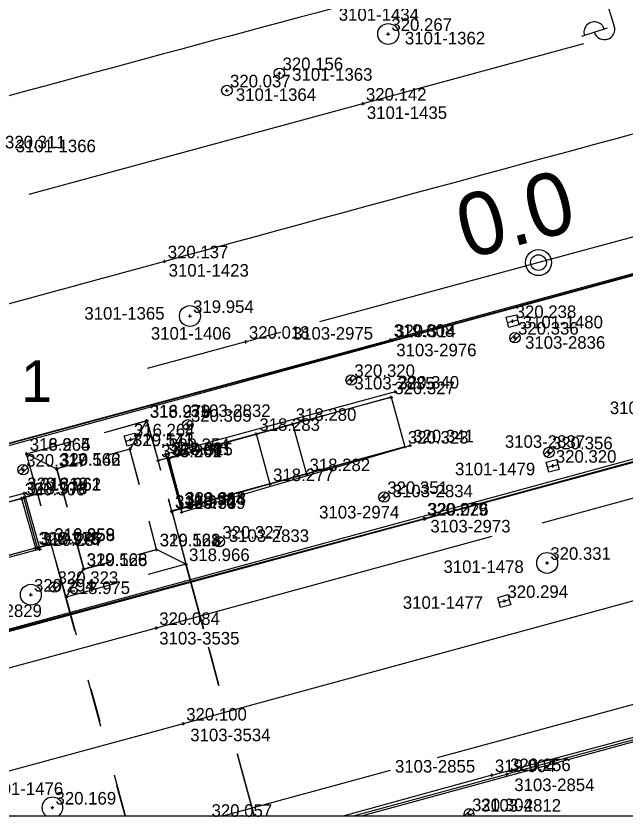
# Model space of a CAD drawing. Extents: x -821875 to -821475, y -1070280 to -1069975.
# Drawn here: x -821747.03 to -821717.84, y -1070250.06 to -1070211.76 of the extents above; entities that cross this region are included whole.
import ezdxf

# ---------------------------------------------------------------- set-up
doc = ezdxf.new("R2010")
doc.units = 0
for name, color, linetype in [('Vrstva 1', 7, 'Continuous'), ('Vrstva 14', 7, 'Continuous'), ('Vrstva 17', 7, 'Continuous'), ('Vrstva 18', 7, 'Continuous'), ('Vrstva 25', 7, 'Continuous'), ('Vrstva 3', 7, 'Continuous'), ('Vrstva 36', 7, 'Continuous'), ('Vrstva 43', 7, 'Continuous'), ('Vrstva 51', 7, 'Continuous'), ('Vrstva 60', 7, 'Continuous'), ('Vrstva 61', 7, 'Continuous'), ('Vrstva 7', 7, 'Continuous')]:
    doc.layers.add(name, color=color, linetype=linetype)

# ---------------------------------------------------------------- blocks, each defined once
blk = doc.blocks.new('BOD')
at = {"layer": 'Vrstva 3'}
for p, q in [((-0.15, 0), (0.15, 0)), ((0, -0.15), (0, 0.15))]:
    blk.add_line(p, q, dxfattribs=at)

msp = doc.modelspace()

# ---------------------------------------------------------------- linework, layer by layer
at = {"layer": 'Vrstva 1'}
msp.add_line((-821704.713, -1070218.861), (-821732.499, -1070226.383), dxfattribs=at)
msp.add_lwpolyline([(-821500, -1070000), (-821850, -1070000), (-821850, -1070250), (-821500, -1070250)], close=True, dxfattribs=at)
msp.add_lwpolyline([(-821500, -1070000), (-821850, -1070000), (-821850, -1070250), (-821500, -1070250)], close=True, dxfattribs=at)
for points in [[(-821719.872, -1070213.081), (-821746.41, -1070220.298)], [(-821682.027, -1070225.161), (-821721.87, -1070236.004)], [(-821667.464, -1070226.079), (-821669.621, -1070226.661), (-821739.032, -1070245.599)], [(-821724.264, -1070236.655), (-821740.322, -1070241.025)], [(-821688.161, -1070236.716), (-821726.868, -1070247.228)], [(-821740.322, -1070241.025), (-821750.102, -1070243.674)], [(-821739.032, -1070245.599), (-821755.257, -1070250)], [(-821729.131, -1070247.842), (-821737.076, -1070250)]]:
    msp.add_lwpolyline(points, dxfattribs=at)
for points in [[(-821710.276, -1070200.761), (-821741.264, -1070209.238), (-821760.235, -1070214.402), (-821776.338, -1070219.041), (-821794.464, -1070225.772), (-821811.866, -1070233.595), (-821823.5, -1070239.204)], [(-821742.542, -1070204.561), (-821755.391, -1070207.946), (-821768.915, -1070211.875), (-821773.964, -1070213.578)], [(-821709.336, -1070205.287), (-821731.872, -1070211.395), (-821757.763, -1070218.461), (-821767.367, -1070221.229)], [(-821705.268, -1070214.096), (-821739.917, -1070223.49), (-821760.504, -1070229.155), (-821769.875, -1070231.779)], [(-821734.361, -1070226.887), (-821736.033, -1070227.34), (-821740.744, -1070228.619)]]:
    msp.add_spline(points, degree=3, dxfattribs=at)
at = {"layer": 'Vrstva 14'}
for p, q in [((-821664.962, -1070209.896), (-821757.694, -1070235.105)), ((-821687.531, -1070215.9), (-821729.11, -1070227.249)), ((-821729.033, -1070227.268), (-821687.611, -1070215.993)), ((-821768.204, -1070246.736), (-821665.012, -1070218.658)), ((-821684.759, -1070224.159), (-821727.507, -1070235.797)), ((-821727.465, -1070235.8), (-821684.647, -1070224.184)), ((-821729.033, -1070227.268), (-821757.732, -1070234.994)), ((-821757.728, -1070234.967), (-821729.11, -1070227.249)), ((-821727.507, -1070235.797), (-821755.35, -1070243.283)), ((-821755.252, -1070243.318), (-821727.465, -1070235.8)), ((-821680.981, -1070236.519), (-821730.446, -1070250)), ((-821724.263, -1070248.063), (-821681.061, -1070236.453)), ((-821681.085, -1070236.494), (-821723.536, -1070248.016)), ((-821724.263, -1070248.063), (-821731.32, -1070250)), ((-821730.876, -1070250), (-821723.536, -1070248.016))]:
    msp.add_line(p, q, dxfattribs=at)
at = {"layer": 'Vrstva 17'}
for points in [[(-821728.878, -1070229.723), (-821739.859, -1070232.709), (-821739.095, -1070235.477), (-821728.172, -1070232.291)], [(-821757.433, -1070237.436), (-821746.637, -1070234.581), (-821745.884, -1070237.251), (-821756.709, -1070240.158)]]:
    msp.add_lwpolyline(points, dxfattribs=at)
at = {"layer": 'Vrstva 18'}
for points in [[(-821729.076, -1070229.992), (-821739.7, -1070232.918), (-821739.759, -1070232.897), (-821740.224, -1070233.006), (-821740.229, -1070233.009)], [(-821742.799, -1070231.675), (-821740.776, -1070231.121), (-821740.224, -1070233.006)], [(-821742.797, -1070231.666), (-821740.766, -1070231.104), (-821740.229, -1070233.009)], [(-821740.776, -1070231.121), (-821741.577, -1070232.469), (-821741.58, -1070232.475)], [(-821740.766, -1070231.104), (-821740.776, -1070231.121)], [(-821746.001, -1070234.589), (-821746.519, -1070232.695), (-821744.38, -1070232.109)], [(-821746.005, -1070234.604), (-821746.517, -1070232.694), (-821744.186, -1070232.05)], [(-821728.425, -1070232.355), (-821739.071, -1070235.273), (-821739.123, -1070235.308), (-821739.564, -1070235.427), (-821739.57, -1070235.452)], [(-821746.517, -1070232.694), (-821746.519, -1070232.695)], [(-821746.519, -1070232.695), (-821745.084, -1070233.412), (-821745.066, -1070233.409)], [(-821741.58, -1070232.475), (-821742.698, -1070232.775)], [(-821741.122, -1070234.175), (-821741.577, -1070232.469), (-821742.563, -1070232.734)], [(-821741.136, -1070234.137), (-821741.58, -1070232.475)], [(-821743.911, -1070233.097), (-821745.084, -1070233.412)], [(-821743.828, -1070233.077), (-821745.066, -1070233.409), (-821744.578, -1070235.24)], [(-821740.092, -1070233.492), (-821740.224, -1070233.006)], [(-821739.759, -1070232.897), (-821739.123, -1070235.308)], [(-821739.071, -1070235.273), (-821739.7, -1070232.918)], [(-821745.084, -1070233.412), (-821744.6, -1070235.212)], [(-821757.178, -1070237.66), (-821746.762, -1070234.831), (-821746.658, -1070234.777), (-821746.001, -1070234.589)], [(-821746.005, -1070234.604), (-821746.001, -1070234.589)], [(-821746.001, -1070234.589), (-821745.84, -1070235.176)], [(-821746.762, -1070234.831), (-821746.098, -1070237.192)], [(-821746, -1070237.183), (-821746.658, -1070234.777)], [(-821739.564, -1070235.427), (-821739.72, -1070234.854)], [(-821739.564, -1070235.427), (-821738.898, -1070237.973), (-821740.697, -1070238.468)], [(-821739.57, -1070235.452), (-821738.051, -1070241.063)], [(-821741.196, -1070237.502), (-821740.298, -1070237.262), (-821740.63, -1070236.018)], [(-821741.104, -1070237.487), (-821740.299, -1070237.27), (-821740.66, -1070235.918)], [(-821745.43, -1070236.675), (-821745.337, -1070237.015)], [(-821744.21, -1070236.623), (-821743.787, -1070238.211), (-821742.528, -1070237.871)], [(-821744.207, -1070236.678), (-821743.798, -1070238.198), (-821742.451, -1070237.838)], [(-821756.527, -1070240.021), (-821746.098, -1070237.192), (-821746, -1070237.183), (-821745.337, -1070237.015)], [(-821745.346, -1070237.001), (-821745.337, -1070237.015)], [(-821744.213, -1070241.16), (-821745.346, -1070237.001)], [(-821742.207, -1070238.884), (-821744.62, -1070239.549), (-821745.337, -1070237.015)], [(-821738.898, -1070237.973), (-821740.298, -1070237.262), (-821740.299, -1070237.27)], [(-821738.057, -1070241.071), (-821738.898, -1070237.973)], [(-821744.62, -1070239.549), (-821743.798, -1070238.198), (-821743.787, -1070238.211)], [(-821744.128, -1070241.361), (-821744.62, -1070239.549)], [(-821737.317, -1070243.793), (-821737.82, -1070241.943)], [(-821737.786, -1070242.043), (-821737.318, -1070243.77)], [(-821742.969, -1070245.726), (-821743.569, -1070243.523)], [(-821743.006, -1070245.496), (-821743.427, -1070243.943)], [(-821736.437, -1070247.026), (-821735.632, -1070250)], [(-821735.632, -1070250), (-821736.428, -1070247.07)], [(-821741.783, -1070250), (-821742.309, -1070248.061)], [(-821741.805, -1070250), (-821742.2, -1070248.548)]]:
    msp.add_lwpolyline(points, dxfattribs=at)
at = {"layer": 'Vrstva 25'}
for p, q in [((-821718.935, -1070210.57), (-821718.402, -1070212.237)), ((-821718.735, -1070212.343), (-821719.971, -1070212.74)), ((-821734.449, -1070214.495), (-821734.399, -1070214.495)), ((-821736.961, -1070215.319), (-821736.911, -1070215.319))]:
    msp.add_line(p, q, dxfattribs=at)
for centre in [(-821734.424, -1070214.495), (-821736.936, -1070215.319)]:
    msp.add_circle(centre, 0.25, dxfattribs=at)
for centre, start, end in [((-821719.354, -1070212.536), 17.1031, 198.5083), ((-821718.876, -1070212.389), 197.8057, 17.8057)]:
    msp.add_arc(centre, 0.5, start, end, dxfattribs=at)
at = {"layer": 'Vrstva 36'}
for p, q in [((-821723.386, -1070227.233), (-821723.064, -1070226.91)), ((-821723.256, -1070227.368), (-821722.929, -1070227.04)), ((-821731.218, -1070229.258), (-821730.896, -1070228.935)), ((-821731.088, -1070229.393), (-821730.761, -1070229.066)), ((-821739.036, -1070231.401), (-821738.714, -1070231.078)), ((-821738.906, -1070231.536), (-821738.579, -1070231.208)), ((-821721.76, -1070232.722), (-821721.438, -1070232.399)), ((-821721.63, -1070232.857), (-821721.303, -1070232.53)), ((-821746.92, -1070233.547), (-821746.596, -1070233.224)), ((-821746.79, -1070233.682), (-821746.462, -1070233.354)), ((-821729.642, -1070234.854), (-821729.32, -1070234.531)), ((-821729.512, -1070234.989), (-821729.185, -1070234.662)), ((-821737.534, -1070236.991), (-821737.21, -1070236.668)), ((-821737.404, -1070237.126), (-821737.076, -1070236.798)), ((-821745.416, -1070239.156), (-821745.092, -1070238.833)), ((-821745.286, -1070239.291), (-821744.958, -1070238.964)), ((-821725.561, -1070250), (-821725.26, -1070249.7)), ((-821725.296, -1070250), (-821725.126, -1070249.83))]:
    msp.add_line(p, q, dxfattribs=at)
for centre in [(-821723.156, -1070227.141), (-821730.988, -1070229.166), (-821738.806, -1070231.309), (-821721.53, -1070232.63), (-821746.689, -1070233.455), (-821729.412, -1070234.762), (-821737.303, -1070236.899), (-821745.185, -1070239.064)]:
    msp.add_circle(centre, 0.25, dxfattribs=at)
msp.add_arc((-821725.353, -1070249.931), 0.25, 343.9784, 196.0216, dxfattribs=at)
at = {"layer": 'Vrstva 43'}
for points in [[(-821723.513, -1070226.408), (-821723.573, -1070226.165), (-821723.087, -1070226.045), (-821722.967, -1070226.531), (-821723.453, -1070226.651), (-821723.513, -1070226.408), (-821723.027, -1070226.288)], [(-821741.773, -1070232.081), (-821741.844, -1070231.841), (-821741.364, -1070231.699), (-821741.222, -1070232.179), (-821741.702, -1070232.321), (-821741.773, -1070232.081), (-821741.293, -1070231.939)], [(-821721.591, -1070233.332), (-821721.655, -1070233.09), (-821721.171, -1070232.962), (-821721.043, -1070233.446), (-821721.527, -1070233.574), (-821721.591, -1070233.332), (-821721.107, -1070233.204)], [(-821723.423, -1070239.669), (-821723.357, -1070239.909), (-821723.839, -1070240.041), (-821723.971, -1070239.559), (-821723.489, -1070239.427), (-821723.423, -1070239.669), (-821723.905, -1070239.799)]]:
    msp.add_lwpolyline(points, dxfattribs=at)
for centre in [(-821729.217, -1070212.617), (-821738.704, -1070226.104), (-821721.614, -1070237.912), (-821746.314, -1070239.43)]:
    msp.add_circle(centre, 0.5, dxfattribs=at)
msp.add_arc((-821745.284, -1070249.615), 0.5, 309.6461, 230.3539, dxfattribs=at)
at = {"layer": 'Vrstva 51'}
for points in [[(-821733.791, -1070231.265), (-821729.076, -1070229.992), (-821728.425, -1070232.355), (-821733.132, -1070233.672)], [(-821735.532, -1070231.745), (-821733.791, -1070231.265), (-821733.132, -1070233.672), (-821734.876, -1070234.15)], [(-821740.229, -1070233.009), (-821735.532, -1070231.745), (-821734.876, -1070234.15), (-821739.57, -1070235.452), (-821739.729, -1070234.863)], [(-821740.118, -1070233.421), (-821740.229, -1070233.009)], [(-821750.714, -1070235.894), (-821746.005, -1070234.604), (-821745.854, -1070235.153)], [(-821745.448, -1070236.63), (-821745.346, -1070237.001), (-821750.05, -1070238.283)]]:
    msp.add_lwpolyline(points, dxfattribs=at)
at = {"layer": 'Vrstva 60'}
for p, q in [((-821725.428, -1070249.931), (-821725.278, -1070249.931)), ((-821725.353, -1070250), (-821725.353, -1070249.856))]:
    msp.add_line(p, q, dxfattribs=at)
at = {"layer": 'Vrstva 7'}
for radius in [0.623, 0.376]:
    msp.add_circle((-821722.028, -1070223.548), radius, dxfattribs=at)

# ---------------------------------------------------------------- block references
at = {"layer": 'Vrstva 60', "xscale": 0.5, "yscale": 0.5}
for p in [(-821729.217, -1070212.617), (-821734.424, -1070214.495), (-821736.936, -1070215.319), (-821730.434, -1070215.953), (-821739.917, -1070223.49), (-821738.704, -1070226.104), (-821723.27, -1070226.348), (-821736.033, -1070227.34), (-821729.11, -1070227.249), (-821729.033, -1070227.268), (-821723.156, -1070227.141), (-821730.988, -1070229.166), (-821728.878, -1070229.723), (-821729.076, -1070229.992), (-821740.776, -1070231.121), (-821740.766, -1070231.104), (-821733.791, -1070231.265), (-821738.806, -1070231.309), (-821741.533, -1070232.01), (-821735.532, -1070231.745), (-821728.425, -1070232.355), (-821728.172, -1070232.291), (-821746.519, -1070232.695), (-821746.517, -1070232.694), (-821741.58, -1070232.475), (-821741.577, -1070232.469), (-821739.859, -1070232.709), (-821721.53, -1070232.63), (-821740.229, -1070233.009), (-821740.224, -1070233.006), (-821739.759, -1070232.897), (-821739.7, -1070232.918), (-821746.689, -1070233.455), (-821745.084, -1070233.412), (-821745.066, -1070233.409), (-821721.349, -1070233.268), (-821733.132, -1070233.672), (-821734.876, -1070234.15), (-821746.637, -1070234.581), (-821746.005, -1070234.604), (-821746.001, -1070234.589), (-821746.762, -1070234.831), (-821746.658, -1070234.777), (-821729.412, -1070234.762), (-821739.57, -1070235.452), (-821739.564, -1070235.427), (-821739.123, -1070235.308), (-821739.095, -1070235.477), (-821739.071, -1070235.273), (-821727.507, -1070235.797), (-821727.465, -1070235.8), (-821745.346, -1070237.001), (-821745.337, -1070237.015), (-821737.303, -1070236.899), (-821746.098, -1070237.192), (-821746, -1070237.183), (-821745.884, -1070237.251), (-821740.299, -1070237.27), (-821740.298, -1070237.262), (-821738.898, -1070237.973), (-821721.614, -1070237.912), (-821743.798, -1070238.198), (-821743.787, -1070238.211), (-821745.185, -1070239.064), (-821746.314, -1070239.43), (-821744.62, -1070239.549), (-821723.664, -1070239.734), (-821740.322, -1070241.025), (-821739.032, -1070245.599), (-821724.263, -1070248.063), (-821723.536, -1070248.016), (-821745.284, -1070249.615)]:
    msp.add_blockref('BOD', p, dxfattribs=at)

# ---------------------------------------------------------------- texts
at = {"layer": 'Vrstva 1'}
msp.add_text('detail 1', height=2, dxfattribs=at).set_placement((-821753.921, -1070230.216))
at = {"layer": 'Vrstva 60'}
for s, p in [('3101-1434', (-821731.583, -1070211.984)), ('3101-1362', (-821728.417, -1070213.114)), ('3101-1363', (-821733.809, -1070214.852)), ('3101-1364', (-821736.507, -1070215.816)), ('3101-1435', (-821730.238, -1070216.681)), ('3101-1366', (-821747.042, -1070218.27)), ('3101-1423', (-821739.722, -1070224.218)), ('3101-1365', (-821743.755, -1070226.276)), ('3101-1480', (-821722.783, -1070226.694)), ('3101-1406', (-821740.573, -1070227.234)), ('3103-2975', (-821733.781, -1070227.233)), ('3103-2836', (-821722.67, -1070227.669)), ('3103-2976', (-821728.831, -1070228.029)), ('3103-2835', (-821730.838, -1070229.616)), ('3103-2832', (-821738.682, -1070230.93)), ('3103-2838', (-821718.613, -1070230.793)), ('3103-2837', (-821723.636, -1070232.407)), ('3101-1479', (-821726.021, -1070233.718)), ('3103-2834', (-821729.003, -1070234.772)), ('3103-2974', (-821732.523, -1070235.784)), ('3103-2973', (-821727.201, -1070236.454)), ('3103-2833', (-821736.842, -1070236.909)), ('3101-1478', (-821726.571, -1070238.389)), ('3101-1477', (-821728.518, -1070240.106)), ('3103-2829', (-821749.623, -1070240.498)), ('3103-3535', (-821740.172, -1070241.812)), ('3103-3534', (-821738.688, -1070246.437)), ('3103-2855', (-821728.894, -1070247.936)), ('3101-1476', (-821748.606, -1070249.005)), ('3103-2854', (-821723.186, -1070248.822)), ('3103-2812', (-821724.785, -1070249.803))]:
    msp.add_text(s, height=0.6, dxfattribs=at).set_placement(p)
at = {"layer": 'Vrstva 61'}
for s, p in [('320.267', (-821729.067, -1070212.467)), ('320.156', (-821734.274, -1070214.345)), ('320.037', (-821736.786, -1070215.169)), ('320.142', (-821730.284, -1070215.803)), ('320.311', (-821747.553, -1070218.087)), ('320.137', (-821739.767, -1070223.34)), ('319.954', (-821738.554, -1070225.954)), ('320.238', (-821723.12, -1070226.198)), ('320.018', (-821735.883, -1070227.19)), ('319.808', (-821728.96, -1070227.099)), ('320.314', (-821728.883, -1070227.118)), ('320.336', (-821723.006, -1070226.991)), ('320.320', (-821730.838, -1070229.016)), ('320.327', (-821728.926, -1070229.842)), ('320.340', (-821728.728, -1070229.573)), ('318.978', (-821740.626, -1070230.971)), ('316.279', (-821740.616, -1070230.954)), ('320.305', (-821738.656, -1070231.159)), ('318.280', (-821733.641, -1070231.115)), ('318.283', (-821735.382, -1070231.595)), ('316.264', (-821741.383, -1070231.86)), ('320.323', (-821728.275, -1070232.205)), ('320.341', (-821728.022, -1070232.141)), ('318.964', (-821746.369, -1070232.545)), ('316.265', (-821746.367, -1070232.544)), ('320.141', (-821741.43, -1070232.325)), ('319.573', (-821741.427, -1070232.319)), ('320.354', (-821739.709, -1070232.559)), ('320.356', (-821721.38, -1070232.48)), ('316.261', (-821740.079, -1070232.859)), ('318.969', (-821740.074, -1070232.856)), ('318.981', (-821739.609, -1070232.747)), ('320.315', (-821739.55, -1070232.768)), ('320.317', (-821746.539, -1070233.305)), ('319.566', (-821744.934, -1070233.262)), ('320.142', (-821744.916, -1070233.259)), ('320.320', (-821721.199, -1070233.118)), ('318.282', (-821732.982, -1070233.522)), ('318.277', (-821734.726, -1070234)), ('320.319', (-821746.487, -1070234.431)), ('316.262', (-821745.855, -1070234.454)), ('318.961', (-821745.851, -1070234.439)), ('320.306', (-821746.612, -1070234.681)), ('318.978', (-821746.508, -1070234.627)), ('320.351', (-821729.262, -1070234.612)), ('318.984', (-821738.973, -1070235.158)), ('320.318', (-821738.921, -1070235.123)), ('316.274', (-821739.42, -1070235.302)), ('318.970', (-821739.414, -1070235.277)), ('320.339', (-821738.945, -1070235.327)), ('320.279', (-821727.357, -1070235.647)), ('320.026', (-821727.315, -1070235.65)), ('320.327', (-821737.153, -1070236.749)), ('320.313', (-821745.948, -1070237.042)), ('318.975', (-821745.85, -1070237.033)), ('320.297', (-821745.734, -1070237.101)), ('316.259', (-821745.196, -1070236.851)), ('318.958', (-821745.187, -1070236.865)), ('320.121', (-821740.149, -1070237.12)), ('319.568', (-821740.148, -1070237.112)), ('318.966', (-821738.748, -1070237.823)), ('320.331', (-821721.464, -1070237.762)), ('319.566', (-821743.648, -1070238.048)), ('320.128', (-821743.637, -1070238.061)), ('320.323', (-821745.035, -1070238.914)), ('320.294', (-821746.164, -1070239.28)), ('318.975', (-821744.47, -1070239.399)), ('320.294', (-821723.514, -1070239.584)), ('320.084', (-821740.172, -1070240.875)), ('320.100', (-821738.882, -1070245.449)), ('320.256', (-821723.386, -1070247.866)), ('319.904', (-821724.113, -1070247.913)), ('320.169', (-821745.134, -1070249.465)), ('320.304', (-821725.203, -1070249.781)), ('320.057', (-821737.67, -1070250.052))]:
    msp.add_text(s, height=0.6, dxfattribs=at).set_placement(p)
at = {"layer": 'Vrstva 7'}
msp.add_text('0.0', height=3, rotation=15.1482, dxfattribs=at).set_placement((-821725.447, -1070223.393))

doc.saveas('drawing.dxf')
